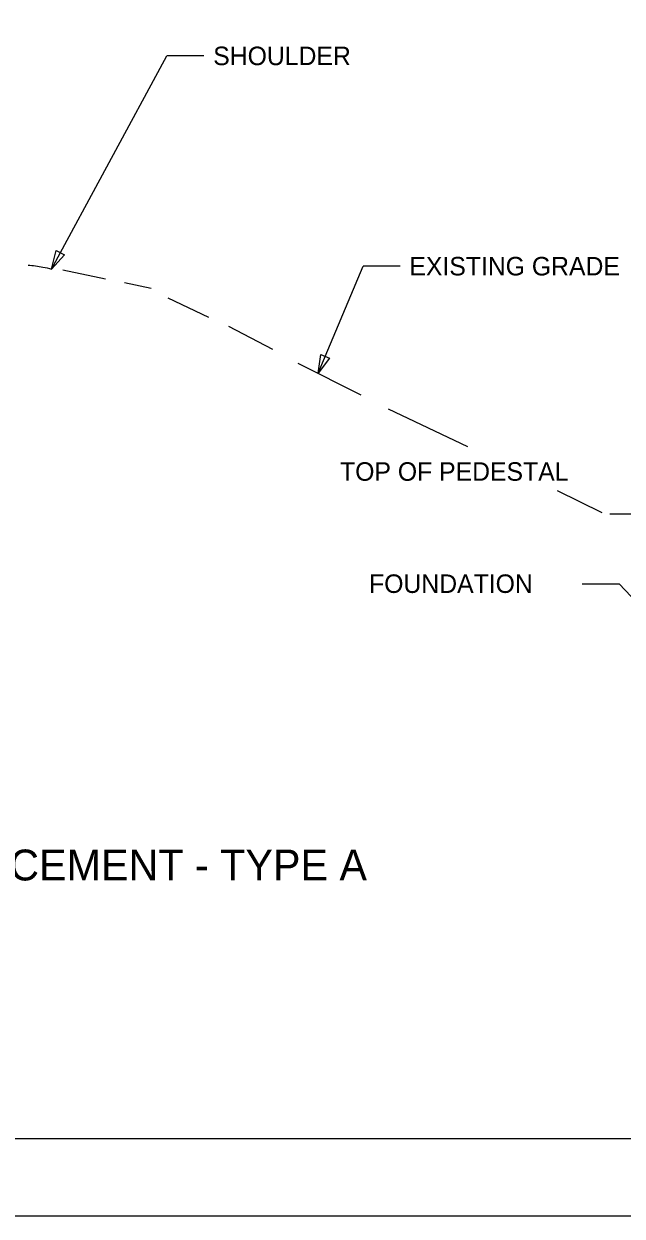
# Model space of a CAD drawing. Extents: x 1299104.8 to 1299141.6, y 239639.8 to 239661.8.
# Drawn here: x 1299111.4 to 1299115.27, y 239639.79 to 239647.52 of the extents above; entities that cross this region are included whole.
import ezdxf

# ---------------------------------------------------------------- set-up
doc = ezdxf.new("R2010")
doc.units = 0
for name, color, linetype in [('DIM TXT', 7, 'Continuous'), ('GS_plotshape_p', 7, 'Continuous'), ('Level 1', 7, 'Continuous'), ('Level 3', 7, 'Continuous'), ('Level 8', 7, 'Continuous')]:
    doc.layers.add(name, color=color, linetype=linetype)

msp = doc.modelspace()

# ---------------------------------------------------------------- linework, layer by layer
at = {"layer": 'GS_plotshape_p'}
msp.add_lwpolyline([(1299104.8019, 239661.7913), (1299138.8019, 239661.7913), (1299138.8019, 239639.7913), (1299104.8019, 239639.7913)], close=True, dxfattribs=at)
at = {"layer": 'Level 1'}
msp.add_lwpolyline([(1299138.3019, 239640.2913), (1299106.3019, 239640.2913), (1299106.3019, 239661.2913), (1299138.3019, 239661.2913)], close=True, dxfattribs=at)
at = {"layer": 'Level 3'}
for p, q in [((1299111.6508, 239645.9222), (1299111.9271, 239645.863)), ((1299112.0487, 239645.84), (1299112.223, 239645.8038)), ((1299112.3315, 239645.7413), (1299112.5946, 239645.6164)), ((1299112.7229, 239645.5572), (1299113.009, 239645.4092)), ((1299113.1734, 239645.3171), (1299113.5812, 239645.1132)), ((1299113.7588, 239645.0212), (1299114.2718, 239644.7778)), ((1299114.8533, 239644.4916), (1299115.1421, 239644.3495)), ((1299115.5705, 239644.34), (1299115.1945, 239644.34))]:
    msp.add_line(p, q, dxfattribs=at)
msp.add_spline([(1299111.4247, 239645.9535), (1299111.5209, 239645.9403), (1299111.5768, 239645.9272)], degree=3, dxfattribs=at)
at = {"layer": 'Level 8'}
for p, q in [((1299111.5768, 239645.9272), (1299112.3246, 239647.3083)), ((1299112.5646, 239647.3083), (1299112.3246, 239647.3083)), ((1299113.304, 239645.2518), (1299113.5957, 239645.9459)), ((1299113.8357, 239645.9459), (1299113.5957, 239645.9459)), ((1299115.0144, 239643.8889), (1299115.2544, 239643.8889)), ((1299115.758, 239643.3509), (1299115.2544, 239643.8889))]:
    msp.add_line(p, q, dxfattribs=at)
for points in [[(1299111.6603, 239646.0184), (1299111.5768, 239645.9272), (1299111.6076, 239646.047)], [(1299113.3782, 239645.3508), (1299113.304, 239645.2518), (1299113.3228, 239645.3741)]]:
    msp.add_lwpolyline(points, close=True, dxfattribs=at)

# ---------------------------------------------------------------- texts
at = {"layer": 'DIM TXT'}
for s, height, p in [('SHOULDER', 0.12, (1299112.6246, 239647.2483)), ('EXISTING GRADE', 0.12, (1299113.8957, 239645.8859)), ('TOP OF PEDESTAL', 0.12, (1299113.4464, 239644.5556)), ('FOUNDATION ', 0.12, (1299113.6344, 239643.8289)), ('CCTV POLE PLACEMENT - TYPE A', 0.2, (1299109.2072, 239641.9662))]:
    msp.add_text(s, height=height, dxfattribs=at).set_placement(p)

doc.saveas('drawing.dxf')
